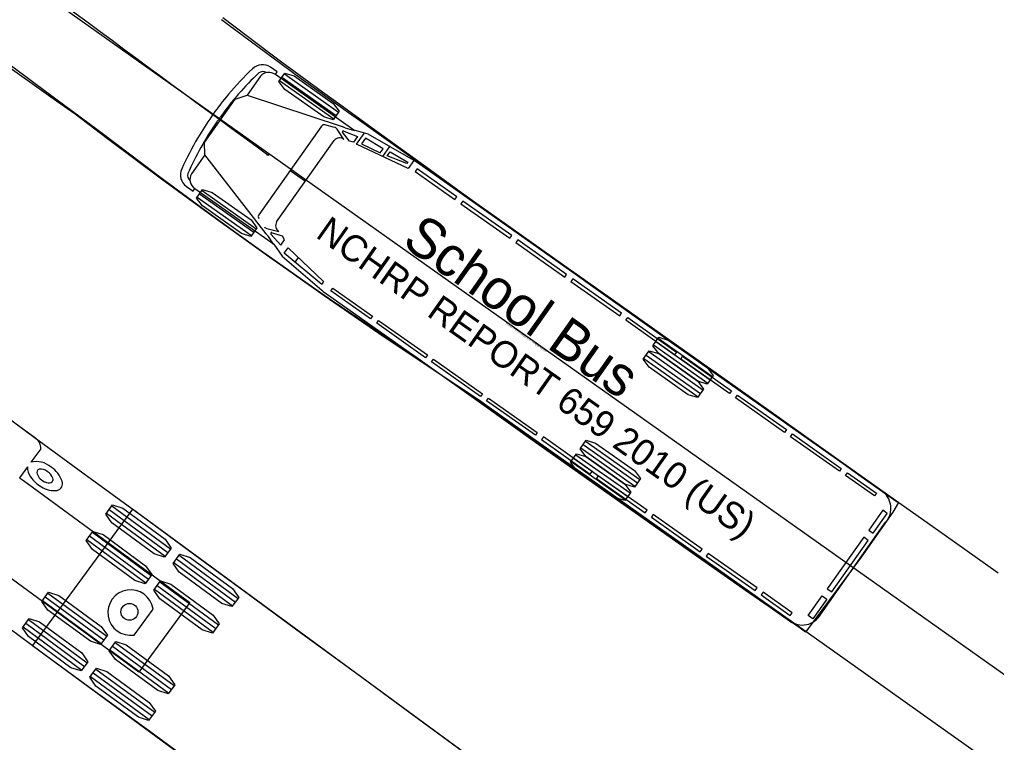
# Model space of a CAD drawing. Extents: x 973688 to 979179, y 703586 to 707602.
# Drawn here: x 978049.64 to 978098.72, y 704307.81 to 704344.11 of the extents above; entities that cross this region are included whole.
import ezdxf

# ---------------------------------------------------------------- set-up
doc = ezdxf.new("R2010")
doc.units = 0
for name, color, linetype in [('NB Left', 7, 'Continuous'), ('NB Right', 7, 'Continuous'), ('SB Left', 7, 'Continuous')]:
    doc.layers.add(name, color=color, linetype=linetype)

msp = doc.modelspace()

# ---------------------------------------------------------------- linework, layer by layer
at = {"layer": 'NB Left'}
for p, q in [((978046.281, 704326.14), (978050.456, 704323.08)), ((978050.709, 704322.558), (978050.21, 704321.877)), ((978050.043, 704321.649), (978049.638, 704321.096)), ((978049.638, 704321.096), (978049.829, 704320.955)), ((978049.829, 704320.955), (978058.187, 704314.83)), ((978055.306, 704319.526), (978052.794, 704316.098)), ((978054.135, 704319.506), (978057.092, 704317.339)), ((978054.27, 704319.691), (978057.228, 704317.524)), ((978093.371, 704291.631), (978055.306, 704319.526)), ((978053.999, 704319.322), (978056.957, 704317.154)), ((978053.024, 704317.991), (978055.981, 704315.823)), ((978053.159, 704318.176), (978056.117, 704316.008)), ((978053.295, 704318.36), (978056.252, 704316.193)), ((978055.628, 704311.337), (978047.27, 704317.462)), ((978057.522, 704317.024), (978060.48, 704314.856)), ((978057.658, 704317.209), (978060.615, 704315.041)), ((978057.387, 704316.839), (978060.344, 704314.672)), ((978052.794, 704316.098), (978050.282, 704312.67)), ((978056.411, 704315.508), (978059.369, 704313.341)), ((978056.547, 704315.693), (978059.504, 704313.526)), ((978056.682, 704315.878), (978059.64, 704313.71)), ((978050.923, 704315.124), (978053.88, 704312.957)), ((978051.058, 704315.309), (978054.016, 704313.141)), ((978050.787, 704314.939), (978053.745, 704312.772)), ((978055.391, 704313.199), (978056.346, 704314.503)), ((978058.187, 704314.83), (978056.908, 704313.083)), ((978049.812, 704313.608), (978052.77, 704311.441)), ((978049.948, 704313.793), (978052.905, 704311.626)), ((978050.083, 704313.978), (978053.041, 704311.811)), ((978056.908, 704313.083), (978055.628, 704311.337)), ((978050.282, 704312.67), (978088.346, 704284.775)), ((978054.311, 704312.641), (978057.268, 704310.474)), ((978054.446, 704312.826), (978057.404, 704310.659)), ((978054.175, 704312.456), (978057.133, 704310.289)), ((978053.2, 704311.126), (978056.157, 704308.958)), ((978053.335, 704311.31), (978056.293, 704309.143)), ((978053.471, 704311.495), (978056.428, 704309.328))]:
    msp.add_line(p, q, dxfattribs=at)
for points in [[(978047.691, 704325.106), (978050.38, 704323.136), (978053.068, 704321.166), (978055.757, 704319.196), (978058.445, 704317.226), (978061.133, 704315.256), (978063.822, 704313.285), (978066.51, 704311.315), (978069.199, 704309.345), (978071.887, 704307.375), (978074.575, 704305.405), (978077.264, 704303.435), (978079.952, 704301.465), (978082.641, 704299.494), (978085.33, 704297.524), (978088.018, 704295.554), (978090.707, 704293.583), (978093.395, 704291.613), (978094.292, 704290.956), (978095.188, 704290.299), (978096.084, 704289.643), (978096.98, 704288.986), (978097.877, 704288.329), (978092.852, 704281.473)], [(978092.852, 704281.473), (978091.956, 704282.13), (978091.06, 704282.787), (978090.164, 704283.443), (978089.267, 704284.1), (978088.371, 704284.757), (978085.682, 704286.727), (978082.994, 704288.698), (978080.305, 704290.668), (978077.617, 704292.638), (978074.928, 704294.608), (978072.24, 704296.579), (978069.551, 704298.549), (978066.863, 704300.519), (978064.174, 704302.489), (978061.486, 704304.459), (978058.798, 704306.429), (978056.109, 704308.4), (978053.421, 704310.37), (978050.732, 704312.34), (978048.044, 704314.31)]]:
    msp.add_lwpolyline(points, dxfattribs=at)
for points in [[(978053.965, 704319.276), (978054.304, 704319.737), (978054.819, 704319.573), (978056.949, 704318.012), (978057.261, 704317.57), (978056.923, 704317.108), (978056.407, 704317.273), (978054.278, 704318.833)], [(978052.99, 704317.945), (978053.328, 704318.406), (978053.844, 704318.242), (978055.974, 704316.681), (978056.286, 704316.239), (978055.948, 704315.778), (978055.432, 704315.942), (978053.302, 704317.502)], [(978057.353, 704316.793), (978057.691, 704317.255), (978058.207, 704317.09), (978060.337, 704315.53), (978060.649, 704315.087), (978060.311, 704314.626), (978059.795, 704314.79), (978057.665, 704316.351)], [(978056.378, 704315.462), (978056.716, 704315.924), (978057.232, 704315.759), (978059.361, 704314.199), (978059.674, 704313.756), (978059.335, 704313.295), (978058.819, 704313.459), (978056.69, 704315.02)], [(978050.754, 704314.893), (978051.092, 704315.355), (978051.608, 704315.19), (978053.737, 704313.63), (978054.049, 704313.187), (978053.711, 704312.726), (978053.195, 704312.89), (978051.066, 704314.451)], [(978049.779, 704313.562), (978050.117, 704314.024), (978050.633, 704313.859), (978052.762, 704312.299), (978053.074, 704311.856), (978052.736, 704311.395), (978052.22, 704311.559), (978050.091, 704313.12)], [(978054.142, 704312.411), (978054.48, 704312.872), (978054.996, 704312.708), (978057.125, 704311.147), (978057.437, 704310.705), (978057.099, 704310.243), (978056.583, 704310.408), (978054.454, 704311.968)], [(978053.166, 704311.08), (978053.504, 704311.541), (978054.02, 704311.377), (978056.15, 704309.816), (978056.462, 704309.374), (978056.124, 704308.912), (978055.608, 704309.077), (978053.478, 704310.637)]]:
    msp.add_lwpolyline(points, close=True, dxfattribs=at)
msp.add_circle((978055.157, 704314.366), 0.424, dxfattribs=at)
for centre, radius, start, end in [((978050.09, 704322.581), 0.619, 357.9252, 53.767), ((978050.487, 704320.775), 1.136, 49.3437, 104.135), ((978050.77, 704321.591), 0.729, 175.4425, 217.9564), ((978050.67, 704321.361), 0.169, 105.2119, 205.3306), ((978050.705, 704321.007), 0.522, 51.5954, 98.7596), ((978050.686, 704320.848), 0.664, 20.6394, 58.8611), ((978050.432, 704320.465), 1.416, 18.7689, 55.8368), ((978051.61, 704322.139), 1.73, 215.1398, 239.9383), ((978051.194, 704321.567), 0.732, 202.3567, 248.5911), ((978051.106, 704321.201), 0.362, 240.4274, 289.4684), ((978051.15, 704321.014), 0.172, 296.3127, 23.4633), ((978051.449, 704320.8), 0.346, 283.3592, 20.3722), ((978051.371, 704321.588), 1.136, 236.4802, 278.001), ((978055.217, 704314.329), 1.143, 8.7649, 278.7649)]:
    msp.add_arc(centre, radius, start, end, dxfattribs=at)
at = {"layer": 'NB Right'}
for p, q in [((978155.389, 704271.361), (978046.776, 704348.262)), ((978062.584, 704341.479), (978062.248, 704341.715)), ((978062.49, 704341.342), (978062.586, 704341.478)), ((978062.586, 704341.478), (978062.584, 704341.479)), ((978061.742, 704341.258), (978061.069, 704340.305)), ((978066.436, 704338.555), (978062.49, 704341.342)), ((978062.7, 704341.04), (978065.423, 704339.117)), ((978062.82, 704341.211), (978065.543, 704339.288)), ((978062.941, 704341.381), (978065.663, 704339.458)), ((978058.935, 704337.935), (978060.473, 704340.114)), ((978060.473, 704340.114), (978061.069, 704340.305)), ((978061.069, 704340.305), (978065.839, 704338.733)), ((978059.321, 704339.295), (978059.279, 704339.236)), ((978059.363, 704339.354), (978059.321, 704339.295)), ((978064.802, 704338.758), (978061.659, 704334.309)), ((978065.469, 704338.693), (978064.983, 704338.818)), ((978065.938, 704338.09), (978065.59, 704338.608)), ((978065.989, 704338.666), (978066.46, 704338.538)), ((978066.448, 704338.549), (978066.436, 704338.555)), ((978067.157, 704338.355), (978066.448, 704338.549)), ((978066.217, 704337.996), (978065.867, 704338.451)), ((978065.928, 704338.505), (978066.61, 704338.228)), ((978066.61, 704338.228), (978066.418, 704337.955)), ((978066.57, 704337.843), (978066.954, 704338.388)), ((978067.013, 704338.147), (978066.821, 704337.875)), ((978067.904, 704337.62), (978067.013, 704338.147)), ((978069.436, 704337.051), (978067.157, 704338.355)), ((978058.953, 704337.31), (978058.935, 704337.935)), ((978062.555, 704333.95), (978065.44, 704338.034)), ((978066.418, 704337.955), (978066.217, 704337.996)), ((978069.158, 704336.627), (978066.57, 704337.843)), ((978066.821, 704337.875), (978067.76, 704337.416)), ((978067.76, 704337.416), (978067.904, 704337.62)), ((978068.217, 704337.735), (978067.864, 704337.235)), ((978058.953, 704337.31), (978058.28, 704336.357)), ((978062.03, 704333.34), (978058.953, 704337.31)), ((978068.115, 704337.267), (978068.259, 704337.471)), ((978069.102, 704336.876), (978068.115, 704337.267)), ((978068.259, 704337.471), (978069.15, 704336.944)), ((978069.15, 704336.944), (978069.102, 704336.876)), ((978069.447, 704337.036), (978069.158, 704336.627)), ((978069.515, 704336.997), (978069.436, 704337.051)), ((978069.905, 704336.722), (978069.515, 704336.997)), ((978069.611, 704336.618), (978069.515, 704336.482)), ((978071.604, 704335.21), (978069.611, 704336.618)), ((978092.933, 704320.457), (978069.905, 704336.722)), ((978063.231, 704336.534), (978063.997, 704335.992)), ((978069.515, 704336.482), (978071.508, 704335.074)), ((978058.019, 704335.727), (978058.354, 704335.489)), ((978058.355, 704335.488), (978058.452, 704335.624)), ((978058.452, 704335.624), (978062.398, 704332.837)), ((978058.354, 704335.489), (978058.355, 704335.488)), ((978058.566, 704335.187), (978061.288, 704333.264)), ((978058.686, 704335.357), (978061.408, 704333.434)), ((978058.806, 704335.527), (978061.529, 704333.604)), ((978071.508, 704335.074), (978071.604, 704335.21)), ((978071.911, 704334.994), (978071.815, 704334.858)), ((978071.815, 704334.858), (978074.268, 704333.125)), ((978074.364, 704333.261), (978071.911, 704334.994)), ((978062.065, 704333.617), (978062.669, 704333.461)), ((978062.404, 704332.833), (978062.143, 704333.221)), ((978062.26, 704333.334), (978062.76, 704332.776)), ((978062.847, 704333.224), (978062.3, 704333.402)), ((978062.952, 704333.048), (978062.847, 704333.224)), ((978074.268, 704333.125), (978074.364, 704333.261)), ((978062.398, 704332.837), (978062.407, 704332.828)), ((978062.407, 704332.828), (978062.827, 704332.224)), ((978062.76, 704332.776), (978062.952, 704333.048)), ((978062.939, 704332.38), (978063.132, 704332.652)), ((978063.132, 704332.652), (978064.915, 704330.947)), ((978074.671, 704333.045), (978074.575, 704332.908)), ((978074.575, 704332.908), (978077.028, 704331.176)), ((978077.124, 704331.312), (978074.671, 704333.045)), ((978062.827, 704332.224), (978064.818, 704330.513)), ((978064.819, 704330.811), (978062.939, 704332.38)), ((978063.634, 704332.163), (978063.479, 704331.944)), ((978077.028, 704331.176), (978077.124, 704331.312)), ((978064.915, 704330.947), (978064.819, 704330.811)), ((978077.431, 704331.095), (978077.335, 704330.959)), ((978077.335, 704330.959), (978079.788, 704329.226)), ((978079.884, 704329.363), (978077.431, 704331.095)), ((978064.818, 704330.513), (978064.895, 704330.456)), ((978064.895, 704330.456), (978065.285, 704330.181)), ((978065.28, 704330.486), (978065.376, 704330.622)), ((978067.273, 704329.078), (978065.28, 704330.486)), ((978065.376, 704330.622), (978067.369, 704329.214)), ((978065.285, 704330.181), (978088.313, 704313.916)), ((978067.369, 704329.214), (978067.273, 704329.078)), ((978079.788, 704329.226), (978079.884, 704329.363)), ((978067.58, 704328.861), (978067.676, 704328.997)), ((978070.033, 704327.129), (978067.58, 704328.861)), ((978067.676, 704328.997), (978070.129, 704327.265)), ((978080.094, 704329.01), (978080.191, 704329.146)), ((978082.548, 704327.277), (978080.094, 704329.01)), ((978080.191, 704329.146), (978082.644, 704327.413)), ((978081.487, 704327.771), (978084.209, 704325.848)), ((978081.607, 704327.942), (978084.33, 704326.019)), ((978081.727, 704328.112), (978084.45, 704326.189)), ((978070.129, 704327.265), (978070.033, 704327.129)), ((978081.126, 704327.261), (978083.849, 704325.338)), ((978081.246, 704327.431), (978083.969, 704325.508)), ((978082.644, 704327.413), (978082.548, 704327.277)), ((978070.339, 704326.912), (978070.436, 704327.048)), ((978072.793, 704325.179), (978070.339, 704326.912)), ((978070.436, 704327.048), (978072.889, 704325.315)), ((978081.006, 704327.091), (978083.729, 704325.168)), ((978082.854, 704327.061), (978082.95, 704327.197)), ((978085.307, 704325.328), (978082.854, 704327.061)), ((978082.95, 704327.197), (978085.403, 704325.464)), ((978072.889, 704325.315), (978072.793, 704325.179)), ((978085.403, 704325.464), (978085.307, 704325.328)), ((978073.099, 704324.963), (978073.195, 704325.099)), ((978075.552, 704323.23), (978073.099, 704324.963)), ((978073.195, 704325.099), (978075.649, 704323.366)), ((978085.614, 704325.111), (978085.71, 704325.248)), ((978088.067, 704323.379), (978085.614, 704325.111)), ((978085.71, 704325.248), (978088.163, 704323.515)), ((978075.649, 704323.366), (978075.552, 704323.23)), ((978088.163, 704323.515), (978088.067, 704323.379)), ((978075.955, 704323.15), (978075.859, 704323.013)), ((978075.859, 704323.013), (978078.312, 704321.281)), ((978078.408, 704321.417), (978075.955, 704323.15)), ((978078.073, 704322.939), (978080.796, 704321.016)), ((978088.374, 704323.162), (978088.47, 704323.298)), ((978090.827, 704321.429), (978088.374, 704323.162)), ((978088.47, 704323.298), (978090.923, 704321.566)), ((978077.833, 704322.598), (978080.556, 704320.675)), ((978077.953, 704322.769), (978080.676, 704320.845)), ((978077.352, 704321.918), (978080.075, 704319.995)), ((978077.472, 704322.088), (978080.195, 704320.165)), ((978077.593, 704322.258), (978080.315, 704320.335)), ((978078.312, 704321.281), (978078.408, 704321.417)), ((978090.923, 704321.566), (978090.827, 704321.429)), ((978078.715, 704321.2), (978078.619, 704321.064)), ((978078.619, 704321.064), (978081.072, 704319.332)), ((978081.168, 704319.468), (978078.715, 704321.2)), ((978091.134, 704321.213), (978091.23, 704321.349)), ((978092.59, 704320.184), (978091.134, 704321.213)), ((978091.23, 704321.349), (978092.686, 704320.32)), ((978092.686, 704320.32), (978092.59, 704320.184)), ((978081.072, 704319.332), (978081.168, 704319.468)), ((978093.003, 704319.468), (978092.3, 704318.471)), ((978093.233, 704319.305), (978093.003, 704319.468)), ((978081.475, 704319.251), (978081.379, 704319.115)), ((978081.379, 704319.115), (978083.832, 704317.382)), ((978083.928, 704317.518), (978081.475, 704319.251)), ((978092.53, 704318.309), (978093.233, 704319.305)), ((978089.891, 704314.247), (978093.15, 704318.862)), ((978092.3, 704318.471), (978092.53, 704318.309)), ((978092.047, 704318.114), (978090.22, 704315.528)), ((978090.45, 704315.365), (978092.277, 704317.952)), ((978092.277, 704317.952), (978092.047, 704318.114)), ((978083.832, 704317.382), (978083.928, 704317.518)), ((978084.235, 704317.302), (978084.138, 704317.166)), ((978084.138, 704317.166), (978086.592, 704315.433)), ((978086.688, 704315.569), (978084.235, 704317.302)), ((978086.592, 704315.433), (978086.688, 704315.569)), ((978090.22, 704315.528), (978090.45, 704315.365)), ((978086.994, 704315.353), (978086.898, 704315.217)), ((978086.898, 704315.217), (978088.355, 704314.188)), ((978088.451, 704314.324), (978086.994, 704315.353)), ((978089.264, 704314.174), (978089.968, 704315.17)), ((978090.198, 704315.008), (978089.494, 704314.012)), ((978089.968, 704315.17), (978090.198, 704315.008)), ((978088.355, 704314.188), (978088.451, 704314.324)), ((978089.494, 704314.012), (978089.264, 704314.174))]:
    msp.add_line(p, q, dxfattribs=at)
for points in [[(978059.783, 704344.111), (978060.836, 704343.324), (978063.222, 704341.564), (978063.488, 704341.369), (978066.17, 704339.435), (978066.71, 704339.05), (978068.879, 704337.514), (978071.598, 704335.589), (978074.318, 704333.663), (978077.039, 704331.737), (978079.759, 704329.811), (978082.48, 704327.885), (978085.2, 704325.959), (978087.921, 704324.033), (978090.641, 704322.107), (978093.362, 704320.181), (978096.083, 704318.255), (978098.803, 704316.329)], [(978059.843, 704344.204), (978062.202, 704342.433), (978062.73, 704342.041), (978064.859, 704340.484), (978065.929, 704339.705), (978067.538, 704338.537), (978070.226, 704336.592), (978071.841, 704335.427), (978072.919, 704334.652), (978075.619, 704332.716), (978077.783, 704331.171), (978078.325, 704330.785), (978081.036, 704328.858), (978083.754, 704326.935), (978086.476, 704325.013), (978089.199, 704323.09), (978090.106, 704322.449), (978091.014, 704321.808), (978091.921, 704321.167), (978092.829, 704320.526), (978093.736, 704319.885), (978093.788, 704319.848), (978093.509, 704319.37)], [(978093.509, 704319.37), (978091.916, 704317.114), (978089.121, 704313.35), (978088.847, 704313.54), (978087.934, 704314.174), (978087.022, 704314.809), (978086.111, 704315.444), (978085.2, 704316.08), (978083.743, 704317.099), (978081.015, 704319.014), (978079.379, 704320.167), (978078.289, 704320.937), (978075.565, 704322.866), (978072.843, 704324.803), (978070.123, 704326.747), (978069.579, 704327.135), (978067.354, 704328.62), (978065.146, 704330.125), (978064.596, 704330.504), (978061.865, 704332.42), (978060.508, 704333.39), (978059.156, 704334.37), (978056.73, 704336.159), (978056.461, 704336.359), (978053.781, 704338.389), (978053.514, 704338.594), (978051.075, 704340.396), (978048.364, 704342.406)], [(978100.436, 704305.366), (978097.715, 704307.292), (978094.995, 704309.218), (978092.275, 704311.145), (978089.554, 704313.071), (978086.834, 704314.997), (978084.113, 704316.924), (978081.393, 704318.85), (978078.672, 704320.776), (978075.952, 704322.703), (978073.232, 704324.629), (978072.687, 704325.014), (978070.462, 704326.486), (978067.695, 704328.346), (978064.946, 704330.234), (978062.757, 704331.767), (978062.21, 704332.154), (978059.482, 704334.109), (978057.577, 704335.499), (978056.763, 704336.1), (978054.056, 704338.124), (978052.438, 704339.351), (978051.333, 704340.134), (978048.57, 704342.09)]]:
    msp.add_lwpolyline(points, dxfattribs=at)
for points in [[(978062.67, 704340.998), (978062.97, 704341.423), (978063.442, 704341.282), (978065.402, 704339.897), (978065.693, 704339.5), (978065.393, 704339.075), (978064.921, 704339.216), (978062.961, 704340.601)], [(978058.536, 704335.144), (978058.836, 704335.569), (978059.307, 704335.428), (978061.268, 704334.043), (978061.558, 704333.646), (978061.258, 704333.221), (978060.787, 704333.363), (978058.827, 704334.747)], [(978081.457, 704327.729), (978081.757, 704328.154), (978082.228, 704328.013), (978084.189, 704326.628), (978084.48, 704326.231), (978084.18, 704325.806), (978083.708, 704325.947), (978081.748, 704327.332)], [(978080.976, 704327.049), (978081.276, 704327.473), (978081.748, 704327.332), (978083.708, 704325.947), (978083.999, 704325.55), (978083.699, 704325.126), (978083.227, 704325.267), (978081.267, 704326.651)], [(978077.803, 704322.556), (978078.103, 704322.981), (978078.575, 704322.84), (978080.535, 704321.455), (978080.826, 704321.058), (978080.526, 704320.633), (978080.054, 704320.774), (978078.094, 704322.159)], [(978077.322, 704321.875), (978077.622, 704322.3), (978078.094, 704322.159), (978080.054, 704320.774), (978080.345, 704320.377), (978080.045, 704319.952), (978079.573, 704320.094), (978077.613, 704321.478)]]:
    msp.add_lwpolyline(points, close=True, dxfattribs=at)
msp.add_circle((978062.114, 704337.322), 0.0417, dxfattribs=at)
for centre, radius, start, end in [((978976.317, 705591.808), 1552.257, 233.034975, 233.917416), ((978072.92, 704329.595), 16.708, 133.8977, 139.9165), ((978061.841, 704341.109), 0.73, 56.144, 133.8977), ((978061.869, 704341.124), 0.368, 61.3084, 125.245), ((978072.566, 704329.939), 15.841, 133.5257, 144.095), ((978062.158, 704340.924), 0.534, 51.4971, 141.2393), ((978072.009, 704330.363), 15.517, 139.9165, 144.5866), ((978071.982, 704330.324), 15.517, 144.9462, 149.6163), ((978072.482, 704329.999), 15.738, 144.7664, 145.4378), ((978072.482, 704329.999), 15.738, 144.095, 144.7664), ((978072.568, 704329.941), 15.841, 145.4378, 156.0071), ((978064.935, 704338.657), 0.168, 73.4623, 142.8718), ((978065.417, 704338.49), 0.21, 34.1088, 75.4961), ((978073.009, 704329.721), 16.708, 149.6163, 155.6351), ((978065.717, 704337.81), 0.357, 52.3035, 141.0651), ((978065.9, 704338.475), 0.0412, 47.2356, 215.4133), ((978058.454, 704336.313), 0.73, 155.6351, 233.3888), ((978058.449, 704336.282), 0.368, 164.2878, 228.2245), ((978058.734, 704336.077), 0.534, 148.2935, 238.0357), ((978061.799, 704334.217), 0.168, 146.661, 216.0705), ((978062.118, 704333.819), 0.21, 214.0367, 255.424), ((978062.859, 704333.764), 0.357, 148.4677, 237.2293), ((978062.293, 704333.369), 0.0412, 74.1195, 242.2972), ((978092.346, 704319.565), 1.068, 318.8532, 56.646), ((978088.958, 704314.768), 1.068, 232.8869, 330.6796)]:
    msp.add_arc(centre, radius, start, end, dxfattribs=at)
for centre, start_param, end_param in [((978065.789, 704338.383), 1.570455, 2.003947), ((978062.343, 704333.505), 4.279238, 4.71273)]:
    msp.add_ellipse(centre, major_axis=(0.312, -0.221), ratio=0.908168, start_param=start_param, end_param=end_param, dxfattribs=at)
at = {"layer": 'SB Left'}
for centre, radius, start, end in [((978621.574, 705074.454), 961.907, 230.920921, 239.173561), ((978266.959, 704636.917), 399.889, 231.89697, 241.1915)]:
    msp.add_arc(centre, radius, start, end, dxfattribs=at)

# ---------------------------------------------------------------- texts
at = {"layer": 'NB Right'}
for s, height, p in [('NCHRP REPORT 659 2010 (US)', 1.33333, (978064.461, 704333.208)), ('School Bus', 2, (978068.784, 704332.808)), ('(c) 2022 Transoft Solutions, Inc. All rights reserved.', 0.08, (978074.059, 704328.837))]:
    msp.add_text(s, height=height, rotation=324.7664, dxfattribs=at).set_placement(p)

doc.saveas('drawing.dxf')
